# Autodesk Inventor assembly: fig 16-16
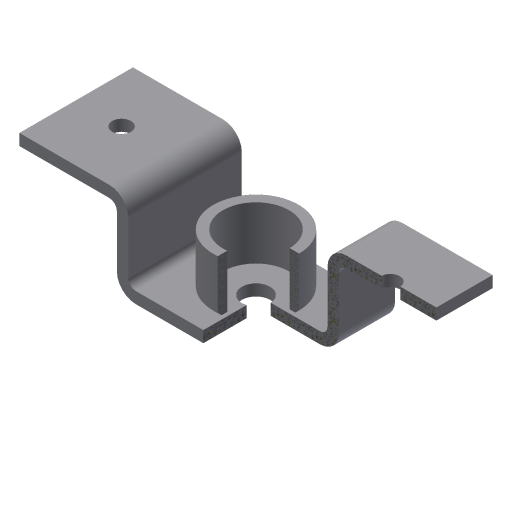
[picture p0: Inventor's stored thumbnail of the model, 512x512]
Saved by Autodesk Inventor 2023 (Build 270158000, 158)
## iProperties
Created: 2005-03
Part Number: fig 16-16
Document SubType Name: Weldment
Designer: CADCIM
Manufacturer: Standard
Standards Organization: Custom
Author: CADCIM
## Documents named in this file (3)
- D:\PROJECTS\Project 2022\Autodesk Inventor For Professional 2023\RESOURCES INVENTOR 2023\RESOURCES INVENTOR 2023\Inventor_2023_Part\Inventor_2023_Part\c16_Inv_2023_prt\fig 16-16\fig 16-16.iam
- D:\PROJECTS\Project 2022\Autodesk Inventor For Professional 2023\RESOURCES INVENTOR 2023\RESOURCES INVENTOR 2023\Inventor_2023_Part\Inventor_2023_Part\c16_Inv_2023_prt\fig 16-16\Bracket.ipt
- D:\PROJECTS\Project 2022\Autodesk Inventor For Professional 2023\RESOURCES INVENTOR 2023\RESOURCES INVENTOR 2023\Inventor_2023_Part\Inventor_2023_Part\c16_Inv_2023_prt\fig 16-16\cylinder.ipt
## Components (2 placed, 2 different names)
1. Bracket:1 — Insert:1
2. cylinder:1 — Insert:1
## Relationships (1: Insert 1)
- Insert:1: Bracket:1 ↔ cylinder:1
